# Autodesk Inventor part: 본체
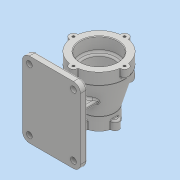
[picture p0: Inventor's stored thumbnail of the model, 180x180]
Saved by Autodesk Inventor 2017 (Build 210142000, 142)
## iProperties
Part Number: 본체
Material: 일반
Document SubType Name: Modeling
Designer: 222
Density: 1 g/cm^3
Appearance: 기본값
Author: 222
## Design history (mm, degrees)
sketch "스케치1"
  geometry: C1 r 44 at (0, 0); 1 further point
  constraints: 1 centre point, 1 coincident
  dimensions: "d0" = 88 diameter of C1
extrude "돌출1" new body sketch "스케치1" distance "d1" = 20; taper "d2" = 0 deg
node "작업 평면1"
sketch "스케치2"
  geometry: C1 r 27.5 at (0, 0); 1 further point
  constraints: 1 centre point, 1 coincident
  dimensions: "d4" = 55 diameter of C1
extrude "돌출2" join sketch "스케치2" distance "d5" = 22; taper "d6" = 0 deg
feature "로프트1" dims "d7" = 0, "d8" = 90 deg, "d9" = 0, "d10" = 90 deg
  node "모서리1"
  node "모서리2"
hole "구멍1" diameter "d13" = 52; stored, may be unused: countersink angle "d17" = 90 deg, drill point angle "d19" = 0 deg; dims "d11" = 10, "d12" = 10, "d14" = 6, "d15" = 64, "d16" = 23, "d18" = 70
hole "구멍2" diameter "d22" = 40; stored, may be unused: countersink angle "d26" = 90 deg, drill point angle "d28" = 0 deg; dims "d20" = 10, "d21" = 10, "d23" = 6, "d24" = 64, "d25" = 23, "d27" = 30
node "작업 평면2"
sketch "스케치3"
  geometry: L1 (50, -115)-(-50, -115); L2 (-50, -115)-(-50, 15); L3 (-50, 15)-(50, 15); L4 (50, 15)-(50, -115); L5 (-27.5, -100)-(27.5, -100) reference; L6 (-44, 0)-(44, 0) reference; L7 (0, -100)-(0, -50); 3 further points
  constraints: 10 end point, 3 midpoint, 2 parallel, 1 horizontal, 1 horizontal alignment, 1 perpendicular, 1 vertical, 1 vertical alignment
  dimensions: "d30" = 100 distance of L2.end L3.end; "d31" = 130 distance of L1.end L2.end; "d32" = 50 distance of L7.start L7.end
extrude "돌출3" join sketch "스케치3" distance "d33" = 12; taper "d34" = 0 deg
sketch "스케치4"
  geometry: L1 (-50, 115)-(50, 115) reference; L2 (50, 115)-(50, -15) reference; L3 (50, -15)-(-50, -15) reference; L4 (-50, -15)-(-50, 115) reference; L5 (-25, 46)-(25, 46); L6 (25, 46)-(25, 54); L7 (25, 54)-(-25, 54); L8 (-25, 54)-(-25, 46); L9 (-4, 26)-(4, 26); L10 (4, 26)-(4, 74); L11 (4, 74)-(-4, 74); L12 (-4, 74)-(-4, 26); 7 further points
  constraints: 16 end point, 6 midpoint, 4 parallel, 2 horizontal, 2 horizontal alignment, 2 perpendicular, 2 vertical alignment
  dimensions: "d35" = 50 distance of L7.end L6.end; "d36" = 8 distance of L6.end L5.end; "d37" = 8 distance of L11.end L10.end; "d38" = 48 distance of L10.end L9.end
extrude "돌출4" join sketch "스케치4" stored distance "d39" = 12; taper "d40" = 0 deg
sketch "스케치5"
  geometry: C1 r 7 at (0, 44); 3 further points
  constraints: 3 vertical alignment, 1 centre point, 2 other
  dimensions: "d41" = 14 diameter of C1
extrude "돌출5" join sketch "스케치5" distance "d42" = 15; taper "d43" = 0 deg
hole "구멍3" diameter "d46" = 4.134; stored, may be unused: countersink angle "d50" = 90 deg, drill point angle "d52" = 118 deg; dims "d44" = 10, "d45" = 10, "d47" = 9, "d48" = 64, "d49" = 23, "d51" = 11
sketch "스케치6"
  geometry: C1 r 7 at (0, 27.5); 2 further points
  constraints: 2 vertical alignment, 1 centre point, 1 other
  dimensions: "d56" = 14 diameter of C1
extrude "돌출6" join sketch "스케치6" distance "d57" = 15; taper "d58" = 0 deg
hole "구멍4" diameter "d61" = 4.134; stored, may be unused: countersink angle "d65" = 90 deg, drill point angle "d67" = 118 deg; dims "d59" = 10, "d60" = 10, "d62" = 9, "d63" = 64, "d64" = 23, "d66" = 11
node "작업 평면3"
sketch "스케치7"
  geometry: L1 (-7, 0)-(7, 0) reference; C1 r 17 at (0, -50); 4 further points
  constraints: 1 centre point, 1 midpoint, 1 vertical alignment
  dimensions: "d72" = 34 diameter of C1; "d73" = 50 distance from line of L1 C1.centre
extrude "돌출7" join sketch "스케치7" stored distance "d74" = 15; taper "d75" = 0 deg
hole "구멍5" diameter "d78" = 22; stored, may be unused: countersink angle "d82" = 90 deg, drill point angle "d84" = 0 deg; dims "d76" = 10, "d77" = 10, "d79" = 9, "d80" = 28, "d81" = 1, "d83" = 30
fillet "모깎기1" dims "d85" = 12
sketch "스케치8"
  geometry: L1 (38, -15)-(-38, -15) reference; L2 (50, 103)-(50, -3) reference; 2 further points
  constraints: 1 other
  dimensions: "d86" = 65 distance from line of point (40, 50) L1; "d87" = 10 distance from line of L2 point (40, 50)
feature "엠보싱1" sketch "스케치8" dims "d0" = 88, "d26" = 90 deg, "d88" = 0.5, "d89" = 0
hole "구멍6" diameter "d92" = 10; stored, may be unused: countersink angle "d96" = 90 deg, drill point angle "d98" = 0 deg; dims "d90" = 10, "d91" = 10, "d93" = 9, "d94" = 28, "d95" = 1, "d97" = 30
hole "구멍7" diameter "d101" = 10; stored, may be unused: countersink angle "d105" = 90 deg, drill point angle "d107" = 0 deg; dims "d99" = 10, "d100" = 10, "d102" = 9, "d103" = 28, "d104" = 1, "d106" = 30
hole "구멍8" diameter "d110" = 10; stored, may be unused: countersink angle "d114" = 90 deg, drill point angle "d116" = 0 deg; dims "d108" = 10, "d109" = 10, "d111" = 9, "d112" = 28, "d113" = 1, "d115" = 30
hole "구멍9" diameter "d119" = 10; stored, may be unused: countersink angle "d123" = 90 deg, drill point angle "d125" = 0 deg; dims "d117" = 10, "d118" = 10, "d120" = 9, "d121" = 28, "d122" = 1, "d124" = 30
fillet "모깎기2" dims "d126" = 3
fillet "모깎기3" dims "d127" = 3
fillet "모깎기4" dims "d128" = 3
fillet "모깎기5" dims "d129" = 3
fillet "모깎기6" dims "d130" = 1
chamfer "모따기1" distance "d131" = 1; stored, may be unused: second distance "d132" = 2, angle "d133" = 45 deg
fillet "모깎기7" dims "d134" = 3
node "솔리드1"
pattern_circular "원형 패턴1" dims angle "d54" = 360 deg
pattern_circular "원형 패턴2" dims angle "d69" = 360 deg
node "투영된 루프1"
other parameters: "d29" = -82, "d71" = 45
